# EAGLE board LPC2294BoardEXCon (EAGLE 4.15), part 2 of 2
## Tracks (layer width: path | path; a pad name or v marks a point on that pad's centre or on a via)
/CS1_RAM  (via drill 0.5)
  Top 0.254: IC1.13 34.44,22.86 v37.46,19.84 40.63,16.66 53.97,16.66 57.93,12.7 IC2.13
  Bottom 0.254: IC3.30 51.56,39.66 49.52,37.62 49.52,34.12 46.03,30.63 46.03,26.82 43.81,24.6 43.81,20.47 43.17,19.84 40.32,19.84 40,20.16 37.78,20.16 v37.46,19.84
/CS2  (via drill 0.5)
  Top 0.254: v49.21,39.2 52.7,39.2 53.65,38.25 55.88,38.25 56.83,37.3 60.64,37.3 62.54,39.2 65.08,39.2 66.35,37.94 68.26,37.94 69.53,39.2 75.88,39.2 78.1,41.43 78.1,50.63 77.78,50.95 77.78,62.7 78.1,63.02 78.1,66.83 78.73,67.46 78.73,79.84 77.78,80.8 67.94,80.8 66.67,82.07 52.38,82.07 52.06,82.38 v52.06,83.65
  Bottom 0.254: IC3.35 49.06,39.35 v49.21,39.2 | IC6.34 51.97,83.56 v52.06,83.65
/CS3  (via drill 0.5)
  Top 0.254: v48.25,38.57 48.57,38.57 48.89,38.25 50.16,38.25 51.11,37.3 52.38,37.3 54.92,34.76 60.95,34.76 62.54,33.17 76.83,33.17 77.78,32.22 78.73,32.22 81.28,34.76 81.28,37.62 82.23,38.57 SV1.39
  Bottom 0.254: IC3.36 48.56,40.15 48.25,39.84 v48.25,38.57
/OE  (via drill 0.5)
  Top 0.254: IC2.42 57.93,23.81 v54.6,27.14 51.11,30.63 42.22,30.63 38.09,34.76 35.24,34.76 34.44,35.56 IC1.42 34.44,48.56 36.51,50.63 36.51,55.4 47.94,66.83 56.83,66.83 v57.78,65.88 | v40.95,70 43.17,72.22 44.45,72.22 47.94,75.72 53.65,75.72 v53.97,76.03 | v78.42,37.94 70.16,37.94 68.89,36.66 65.72,36.66 64.45,37.94 63.18,37.94 62.54,37.3 v62.54,36.98
  Bottom 0.254: IC3.90 57.06,65.16 57.14,65.24 | v57.78,65.88 57.14,65.24 | 57.14,65.24 53.65,68.73 42.54,68.73 41.27,70 v40.95,70 | v53.97,76.03 53.65,76.03 53.34,76.35 51.75,76.35 51.54,76.55 IC6.29 | SV1.28 86.04,52.54 83.5,52.54 78.42,47.46 v78.42,37.94 | v54.6,27.14 54.6,28.41 57.14,30.95 59.05,30.95 62.22,34.12 62.22,36.66 v62.54,36.98
/RES  (via drill 0.5)
  Top 0.254: R6.2 66.04,50.95 65.72,51.27 | v80.64,46.51 80.01,46.51 79.37,45.87 79.37,34.76 78.73,34.12 77.78,34.12 76.51,35.4 v71.12,35.4
  Top 0.406: 65.72,51.27 C3.1 | R6.2 66.04,49.05 v66.35,48.73
  Bottom 0.254: v66.35,48.73 66.67,48.41 66.67,47.78 67.06,47.39 IC3.135 72.14,47.39 72.7,46.83 72.7,37.62 71.12,36.03 v71.12,35.4 | SV1.31 82.86,48.73 v80.64,46.51
/WE  (via drill 0.5)
  Top 0.254: IC1.15 36.04,22.53 v39.36,19.2 41.27,17.3 56.19,17.3 59.53,13.96 IC2.15 | v51.43,38.25 52.7,38.25 53.34,37.62 55.88,37.62 56.83,36.66 60.64,36.66 62.54,38.57 64.77,38.57 66.04,37.3 68.58,37.3 69.84,38.57 76.2,38.57 78.73,41.11 78.73,49.05 v79.05,49.37 78.73,49.68 78.73,50.63 78.42,50.95 78.42,62.7 78.73,63.02 78.73,66.83 79.37,67.46 79.37,80.8 78.73,81.43 68.26,81.43 66.67,83.02 v53.65,83.02
  Bottom 0.254: v39.36,19.2 43.81,19.2 44.45,19.84 44.45,24.6 46.67,26.82 46.67,30.63 50.16,34.12 50.16,36.98 v51.43,38.25 52.06,38.89 52.06,39.2 IC3.29 | IC6.30 50.89,80.26 v53.65,83.02 | SV1.27 83.5,53.81 v79.05,49.37
A0  (via drill 0.5)
  Top 0.254: v39.36,70 40.32,70.95 41.27,70.95 43.17,72.86 44.45,72.86 47.94,76.35 53.02,76.35 53.65,76.99 61.91,76.99 62.54,77.62 65.72,77.62 v66.67,76.67
  Bottom 0.254: IC3.89 56.56,65.19 53.65,68.1 41.27,68.1 v39.36,70 | IC6.5 67.15,77.14 v66.67,76.67 66.67,73.81 67.31,73.18 73.34,73.18 76.83,76.67 SV1.9
A1  (via drill 0.5)
  Top 0.254: v38.09,39.84 38.09,48.41 38.41,48.73 38.41,53.49 39.68,54.76 39.68,57.3 47.3,64.92 v55.56,64.92 | v35.55,67.46 35.87,67.14 42.54,67.14 47.94,72.54 63.49,72.54 v64.45,73.49 64.77,73.18 72.07,73.18 v73.02,74.13
  Bottom 0.254: SJ1.1 39.05,40.79 v38.09,39.84 | IC3.88 56.06,64.47 v55.56,64.92 53.65,66.83 41.27,66.83 40.95,67.14 35.87,67.14 v35.55,67.46 | IC6.7 65.84,74.89 v64.45,73.49 | SV1.8 86.04,77.94 76.83,77.94 v73.02,74.13
A2  (via drill 0.5)
  Top 0.254: IC2.11 56.33,11.44 52.38,15.39 39.68,15.39 32.84,22.24 IC1.11 32.84,27.28 v33.33,27.78 | v34.6,66.51 34.6,67.78 35.24,68.41 35.87,68.41 36.51,67.78 42.54,67.78 47.94,73.18 62.86,73.18 v63.18,73.49 64.13,74.45 64.77,74.45 65.4,73.81 71.43,73.81 v73.02,75.4
  Bottom 0.254: IC3.87 55.56,63.65 53.02,66.19 41.27,66.19 40.95,66.51 v34.6,66.51 | v33.33,27.78 31.75,27.78 26.35,33.17 26.35,61.43 31.43,66.51 v34.6,66.51 | v34.6,66.51 34.6,66.46 | IC6.8 65.2,75.51 v63.18,73.49 | SV1.7 76.83,79.21 v73.02,75.4
A3  (via drill 0.5)
  Top 0.254: IC2.10 55.53,11.61 52.38,14.76 39.68,14.76 32.04,22.4 IC1.10 32.04,31.88 v32.38,32.22 | v33.02,65.56 33.02,67.14 34.92,69.05 36.19,69.05 36.82,68.41 42.54,68.41 47.94,73.81 62.22,73.81 v63.18,74.77 63.49,75.08 65.08,75.08 65.72,74.45 70.8,74.45 v71.43,75.08
  Bottom 0.254: IC3.81 52.56,63.47 50.48,65.56 32.7,65.54 | 32.7,65.54 31.11,65.56 26.98,61.43 26.98,35.08 29.84,32.22 v32.38,32.22 | 32.7,65.54 32.7,65.56 v33.02,65.56 | 63.49,75.08 63.61,75.2 | v63.18,74.77 63.49,75.08 | IC6.9 64.55,76.13 63.49,75.08 | SV1.6 86.04,80.48 76.83,80.48 v71.43,75.08
A4  (via drill 0.5)
  Top 0.254: IC2.9 54.73,11.77 52.38,14.12 39.68,14.12 31.24,22.57 IC1.9 31.24,32.98 v31.43,33.17 | v61.91,74.77 61.59,74.45 47.94,74.45 42.54,69.05 37.14,69.05 36.51,69.68 34.6,69.68 32.06,67.14 v32.06,64.6 | v71.43,76.35 67.94,76.35 67.31,75.72 66.35,75.72 65.4,76.67 v63.49,76.67
  Bottom 0.254: IC3.80 52.06,63.34 50.48,64.92 38.73,64.92 38.41,64.6 v32.06,64.6 30.79,64.6 27.62,61.43 27.62,35.08 29.52,33.17 v31.43,33.17 | IC6.10 63.89,77.07 v63.49,76.67 63.49,76.35 v61.91,74.77 | SV1.5 76.83,81.75 v71.43,76.35
A5  (via drill 0.5)
  Top 0.254: IC2.8 53.93,11.94 52.38,13.49 39.68,13.49 30.44,22.73 IC1.8 30.48,27.46 30.79,27.78 30.79,32.54 30.44,32.89 30.44,34.09 v30.48,34.12
  Bottom 0.254: IC3.74 49.06,63.65 39.68,63.65 37.14,61.11 34.6,61.11 28.25,54.76 28.25,35.08 29.21,34.12 v30.48,34.12
A6  (via drill 0.5)
  Top 0.254: IC2.7 53.13,12.1 52.38,12.85 39.68,12.85 29.64,22.9 IC1.7 29.64,27.57 30.16,28.09 30.16,32.22 29.64,32.74 29.64,34.96 v29.52,35.08
  Bottom 0.254: IC3.73 39.36,62.7 37.13,60.47 34.6,60.48 28.89,54.76 28.89,35.71 v29.52,35.08
A7  (via drill 0.5)
  Top 0.254: IC2.48 53.13,24.8 50.48,27.46 42.22,27.46 38.09,31.59 34.28,31.59 29.64,36.23 IC1.48 29.64,41.54 v29.84,41.74
  Bottom 0.254: v29.84,41.74 29.52,42.06 29.52,54.76 34.6,59.84 38.09,59.84 38.64,60.39 IC3.72
A8  (via drill 0.5)
  Top 0.254: IC2.47 53.93,24.64 50.48,28.09 42.22,28.09 38.09,32.22 34.28,32.22 30.44,36.07 IC1.47 30.44,41.07 v31.11,41.74
  Bottom 0.254: IC3.71 39.09,59.89 38.41,59.21 34.6,59.21 30.16,54.76 30.16,43.65 31.11,42.7 v31.11,41.74
A9  (via drill 0.5)
  Top 0.254: IC2.46 54.73,24.47 50.48,28.73 42.22,28.73 38.09,32.86 34.28,32.86 31.24,35.9 IC1.46 31.24,40.29 v31.43,40.48
  Bottom 0.254: IC3.66 33.42,57.39 30.79,54.76 30.79,43.97 32.06,42.7 32.06,41.11 v31.43,40.48
A10  (via drill 0.5)
  Top 0.254: IC2.45 55.53,24.31 50.48,29.36 42.22,29.36 38.09,33.49 34.28,33.49 32.04,35.74 IC1.45 32.04,39.81 v32.7,40.48
  Bottom 0.254: IC3.65 33.55,56.89 31.43,54.76 31.43,43.97 33.02,42.38 33.02,40.79 v32.7,40.48
A11  (via drill 0.5)
  Top 0.254: IC2.44 56.33,24.14 50.48,30 42.22,30 38.09,34.12 34.28,34.12 32.84,35.57 IC1.44 32.84,39.06 v33.02,39.2
  Bottom 0.254: IC3.64 33.69,56.39 32.06,54.76 32.06,43.97 33.65,42.38 33.65,39.84 v33.02,39.2
A12  (via drill 0.5)
  Top 0.254: IC2.38 61.13,24.42 56.83,28.73 54.29,28.73 51.11,31.9 42.22,31.9 37.64,36.49 IC1.38 37.64,38.39 37.14,38.89 37.14,48.09 37.78,48.73 37.78,54.13 v38.73,55.08
  Bottom 0.254: IC3.63 39.54,55.89 v38.73,55.08
A13  (via drill 0.5)
  Top 0.254: IC2.37 61.93,23.04 61.91,23.01 61.91,24.28 56.83,29.36 54.29,29.36 51.11,32.54 42.22,32.54 38.44,36.32 IC1.37 38.44,38.28 39.05,38.89 39.05,53.49 v40.63,55.08
  Bottom 0.254: IC3.62 40.94,55.39 v40.63,55.08
A14  (via drill 0.5)
  Top 0.254: IC2.36 62.73,24.09 56.83,30 54.29,30 51.11,33.17 42.22,33.17 39.24,36.16 IC1.36 39.24,38.13 39.68,38.57 39.68,52.22 v40,52.54
  Bottom 0.254: IC3.56 40.16,52.39 v40,52.54
A15  (via drill 0.5)
  Top 0.254: IC2.35 63.53,23.93 56.83,30.63 54.29,30.63 51.11,33.81 42.22,33.81 40.04,35.99 IC1.35 40.04,37.97 40.32,38.25 40.32,51.27 v40.63,51.59
  Bottom 0.254: IC3.55 40.93,51.89 v40.63,51.59
A16  (via drill 0.5)
  Top 0.254: IC2.34 64.33,23.76 56.83,31.27 54.29,31.27 51.11,34.44 42.22,34.44 40.95,35.71 40.95,36.98 40.9,37.03 | 40.9,37.03 IC1.34 | 40.9,37.03 40.9,50.27 v41.27,50.63
  Bottom 0.254: IC3.53 41.52,50.89 v41.27,50.63
A17  (via drill 0.5)
  Top 0.254: IC2.21 64.33,12.33 56.83,19.84 41.9,19.84 40.63,21.11 40.63,23.96 40.84,24.17 IC1.21 40.84,28.21 38.09,30.95 33.65,30.95 v33.33,31.27
  Bottom 0.254: v33.33,31.27 34.6,32.54 34.6,46.19 36.8,48.39 IC3.48
A18  (via drill 0.5)
  Top 0.254: IC2.20 63.53,12.5 56.83,19.2 41.9,19.2 40.04,21.07 IC1.20 40.04,28.37 38.09,30.32 34.92,30.32 v34.6,30
  Bottom 0.254: IC3.47 37.25,47.89 35.24,45.87 35.24,30.63 v34.6,30
A19  (via drill 0.5)
  Top 0.254: IC2.19 62.73,12.66 56.83,18.57 41.9,18.57 39.24,21.23 IC1.19 39.24,28.54 38.09,29.68 36.19,29.68 v35.87,29.36
  Bottom 0.254: IC3.46 37.39,47.39 35.87,45.87 v35.87,29.36
A20  (via drill 0.5)
  Top 0.254: IC2.18 61.93,12.83 56.83,17.93 41.9,17.93 38.44,21.4 IC1.18 38.44,28.39 38.09,28.73 v37.14,28.73
  Bottom 0.254: IC3.45 37.52,46.89 36.51,45.87 36.51,30 37.14,29.36 v37.14,28.73
A21  (via drill 0.5)
  Top 0.254: v47.94,35.4 48.25,35.08 51.11,35.08 54.29,31.9 56.83,31.9 61.91,26.82 v62.54,26.82 | IC2.17 61.13,10.17 v61.27,10
  Bottom 0.254: 39.05,45.55 SJ1.3 | IC3.44 39.56,46.39 39.05,45.87 39.05,45.55 | 39.05,45.55 40,45.55 40.32,45.24 40.32,39.84 43.49,36.66 46.67,36.66 v47.94,35.4 | v62.54,26.82 62.54,18.25 60.95,16.66 60.95,12.54 61.27,12.22 v61.27,10
AN0  (via drill 0.5)
  Top 0.254: v56.19,42.38 56.19,38.89 57.14,37.94 60.32,37.94 62.22,39.84 65.72,39.84 v66.35,39.2 | v67.94,27.78 68.58,28.41 78.73,28.41 81.28,30.95 SV1.45
  Bottom 0.254: IC3.23 55.06,41.88 55.56,42.38 v56.19,42.38 | v66.35,39.2 68.26,37.3 68.26,28.41 67.94,28.09 v67.94,27.78
BLS0  (via drill 0.5)
  Top 0.254: v59.68,65.88 59.05,65.88 58.1,64.92 57.46,64.92 56.19,66.19 47.94,66.19 37.14,55.4 37.14,48.73 36.51,48.09 36.51,38.57 36.82,38.25 36.82,36.98 | v78.42,35.4 78.1,35.4 77.15,36.35 70.48,36.35 69.53,35.4 v63.18,35.4 | v55.88,27.78 55.56,28.09 54.29,28.09 51.11,31.27 42.22,31.27 38.09,35.4 37.14,35.4 36.82,35.71 36.82,36.98 | 36.82,36.98 36.84,36.99 IC1.39
  Bottom 0.254: IC3.96 60.06,65.5 v59.68,65.88 | SV1.30 86.04,50 82.86,50 79.69,46.83 79.69,38.89 80.01,38.57 80.01,36.66 78.73,35.4 v78.42,35.4 | v63.18,35.4 63.18,34.44 59.05,30.32 57.14,30.32 55.88,29.05 v55.88,27.78
BLS1  (via drill 0.5)
  Top 0.254: v33.97,26.51 33.65,26.19 33.65,25.23 33.64,25.22 IC1.12 33.64,22.07 39.68,16.03 53.34,16.03 v53.97,15.39 | v78.42,36.66 77.78,36.66 77.47,36.98 70.16,36.98 69.21,36.03 65.08,36.03 v64.45,36.66 | v60.32,21.11 59.68,20.47 49.21,20.47 48.89,20.79 v48.57,20.79
  Bottom 0.254: IC3.97 60.56,66.27 60,66.83 56.19,66.83 53.34,69.68 42.54,69.68 41.27,70.95 35.24,70.95 25.71,61.43 25.71,33.17 32.06,26.82 33.65,26.82 v33.97,26.51 | SV1.29 83.18,51.27 79.05,47.14 79.05,38.89 79.37,38.57 79.37,37.62 v78.42,36.66 | v64.45,36.66 64.77,36.35 64.77,33.81 63.18,32.22 63.18,28.73 60.95,26.51 60.95,21.74 v60.32,21.11 | v48.57,20.79 48.57,16.35 48.89,16.03 53.34,16.03 v53.97,15.39
BLS2  (via drill 0.5)
  Top 0.254: v53.65,33.81 53.65,33.17 54.29,32.54 56.83,32.54 60,29.36 v60.64,29.36 | v60,24.28 60.32,23.96 60.32,23.01 60.33,23.03 IC2.39
  Bottom 0.254: v60,24.28 60,28.73 v60.64,29.36 | IC3.27 53.06,34.4 v53.65,33.81
BLS3  (via drill 0.5)
  Top 0.254: v46.35,6.18 46.98,5.55 56.19,5.55 57.14,6.5 57.14,10.95 57.13,10.96 IC2.12
  Bottom 0.254: IC3.28 52.56,38.12 50.79,36.35 50.79,34.12 47.3,30.63 47.3,26.82 45.08,24.6 45.08,12.85 44.76,12.54 44.76,6.82 45.4,6.18 v46.35,6.18
CLOCK  (via drill 0.5)
  Top 0.254: v33.65,54.45 27.62,54.45 26.98,53.81 26.98,48.41 25.08,46.51 v22.22,46.51 | MMC1.3 20.41,68.64 v20.63,68.41
  Bottom 0.254: IC3.59 41.98,53.89 41.59,53.49 34.6,53.49 v33.65,54.45 | v22.22,46.51 20.63,48.09 v20.63,68.41
CS_CARD  (via drill 0.5)
  Top 0.254: v37.46,62.7 37.46,62.38 33.97,58.89 28.57,58.89 22.22,52.54 v22.22,50 | MMC1.7 22.15,58.64 v22.22,58.57
  Bottom 0.254: IC3.78 51.06,63.38 50.16,64.29 39.05,64.29 v37.46,62.7 | v22.22,50 21.9,50.32 21.9,58.26 v22.22,58.57 22.54,58.89 22.54,61.43 26.98,65.88 R14.1
D0  (via drill 0.5)
  Top 0.254: IC1.22 41.64,23.6 v41.59,23.65 | v75.24,73.81 75.88,74.45 75.88,77.62 75.24,78.26 49.21,78.26 44.76,73.81 43.49,73.81 41.9,72.22 v38.73,72.22 38.41,72.54 R16.1
  Bottom 0.254: IC3.98 61.06,66.4 60,67.46 56.19,67.46 53.02,70.64 45.71,70.64 45.4,70.32 42.54,70.32 40.63,72.22 v38.73,72.22 35.87,72.22 25.08,61.43 25.08,33.17 35.24,23.01 40.95,23.01 v41.59,23.65 | v75.24,73.81 76.83,75.4 85.4,75.4 86.67,76.67 SV1.10 87.94,76.67 88.26,76.99 88.26,77.94 89.53,79.21 D1.A
D1  (via drill 0.5)
  Top 0.254: IC1.24 43.24,23.9 v42.86,23.65 | v76.2,73.18 76.51,73.49 76.51,78.57 76.2,78.89 49.21,78.89 44.76,74.45 43.49,74.45 42.22,73.18 v39.68,73.18 R17.1
  Bottom 0.254: IC3.105 64.56,65.44 60.95,68.73 56.19,68.73 53.02,71.91 44.76,71.91 43.49,73.18 v39.68,73.18 36.19,73.18 24.44,61.43 24.44,33.17 35.24,22.38 41.59,22.38 v42.86,23.65 | v76.2,73.18 77.15,74.13 SV1.11 85.4,74.13 86.67,75.4 87.94,75.4 89.53,76.99 D2.A
D2  (via drill 0.5)
  Top 0.254: IC1.25 44.04,23.56 v42.54,22.06 | v76.83,72.22 77.15,72.54 77.15,78.89 76.51,79.53 49.21,79.53 44.76,75.08 43.49,75.08 42.54,74.13 v40.63,74.13 40.63,75.72 40.95,76.03 R18.1
  Bottom 0.254: IC3.106 65.06,65.58 60.95,69.37 56.19,69.37 53.02,72.54 45.08,72.54 43.49,74.13 v40.63,74.13 36.51,74.13 23.81,61.43 23.81,33.17 35.24,21.74 42.22,21.74 v42.54,22.06 | v76.83,72.22 77.47,72.86 85.4,72.86 86.67,74.13 SV1.12 87.94,74.13 88.58,74.77 D3.A 89.85,74.77
D3  (via drill 0.5)
  Top 0.254: IC1.27 45.64,21.82 44.76,20.79 v42.22,20.79 | v77.78,71.59 77.78,79.21 76.83,80.16 49.21,80.16 44.76,75.72 43.49,75.72 42.86,75.08 v41.59,75.08 41.59,76.99 42.22,77.62 R19.1
  Bottom 0.254: IC3.108 66.06,63.62 65.72,63.97 65.75,65.53 60.95,70 56.19,70 53.02,73.18 45.4,73.18 43.49,75.08 v41.59,75.08 36.82,75.08 23.17,61.43 23.17,33.17 35.24,21.11 41.9,21.11 v42.22,20.79 | v77.78,71.59 SV1.13 85.4,71.59 86.67,72.86 88.58,72.86 88.9,72.54 D4.A
D4  (via drill 0.5)
  Top 0.254: IC1.28 45.64,38.33 43.49,40.48 43.49,49.68 44.13,50.32 44.13,59.21 47.3,62.38 53.97,62.38 54.6,61.75 62.54,61.75 63.18,62.38 68.26,62.38 68.58,62.06 v68.58,61.43 | v73.97,70.32 v77.78,70.32 | v42.54,76.03 42.54,76.35 43.49,77.3 R21.1
  Bottom 0.254: v42.54,76.03 43.49,76.03 45.71,73.81 53.02,73.81 56.19,70.64 73.66,70.64 v73.97,70.32 73.66,70 73.66,63.97 71.12,61.43 v68.58,61.43 68.36,61.22 IC3.109 | v77.78,70.32 85.4,70.32 86.67,71.59 SV1.14 87.94,71.59 89.21,70.32 D5.A 89.85,70.32
D5  (via drill 0.5)
  Top 0.254: IC1.30 44.04,39.29 42.86,40.48 42.86,49.68 43.49,50.32 43.49,59.21 47.3,63.02 54.29,63.02 54.92,62.38 62.22,62.38 62.86,63.02 69.21,63.02 69.84,62.38 v69.84,58.89 | v77.78,69.05 77.47,69.37 v74.93,69.37 | R22.1 44.45,79.84 v44.45,77.3
  Bottom 0.254: IC3.114 68.84,57.89 v69.84,58.89 74.29,63.34 74.29,68.73 v74.93,69.37 74.93,70.64 74.29,71.27 56.19,71.27 53.02,74.45 46.03,74.45 44.45,76.03 v44.45,77.3 | v77.78,69.05 SV1.15 85.4,69.05 86.67,70.32 87.94,70.32 88.58,69.68 88.58,69.05 89.53,68.1 D6.A
D6  (via drill 0.5)
  Top 0.254: v71.12,58.89 71.43,59.21 71.43,62.38 67.94,65.88 62.54,65.88 60,63.34 54.92,63.34 54.6,63.65 47.3,63.65 42.86,59.21 42.86,50.32 42.22,49.68 42.22,40.48 43.49,39.2 43.49,38.25 43.24,38 IC1.31 | v77.78,67.78 76.51,67.78 v75.88,68.41 | v45.4,78.26 45.4,78.57 46.03,79.21 R23.1
  Bottom 0.254: IC3.115 69.61,57.39 v71.12,58.89 74.93,62.7 74.93,67.46 v75.88,68.41 75.88,70.95 74.93,71.91 56.19,71.91 53.02,75.08 46.98,75.08 45.4,76.67 v45.4,78.26 | v77.78,67.78 85.4,67.78 86.67,69.05 SV1.16 87.62,69.05 89.21,67.46 89.21,66.19 89.53,65.88 D7.A 90.17,65.88
D7  (via drill 0.5)
  Top 0.254: IC1.33 41.64,49.73 42.22,50.32 42.22,59.21 47.3,64.29 54.92,64.29 55.24,63.97 59.68,63.97 62.22,66.51 67.94,66.51 72.07,62.38 72.07,58.57 v71.12,57.62 | v47.3,79.84 R24.1
  Bottom 0.254: IC3.116 70.38,56.89 v71.12,57.62 75.56,62.06 75.56,66.19 76.83,67.46 | v47.3,79.84 47.3,77.94 49.52,75.72 53.02,75.72 56.19,72.54 75.24,72.54 76.83,70.95 76.83,67.46 | 76.83,67.46 77.47,66.83 78.42,66.83 78.73,67.14 82.55,67.14 83.18,66.51 SV1.17 85.09,66.51 86.36,67.78 87.94,67.78 88.58,67.14 88.58,64.29 89.21,63.65 D8.A 90.17,63.65
D8  (via drill 0.5)
  Top 0.254: v72.39,57.62 72.7,57.94 72.7,62.38 67.62,67.46 47.94,67.46 35.87,55.4 35.87,50.63 28.84,43.6 IC1.49
  Bottom 0.254: IC3.117 71.15,56.39 v72.39,57.62 76.2,61.43 76.2,63.97 76.83,64.6 78.73,64.6 79.37,65.24 86.04,65.24 SV1.18
D9  (via drill 0.5)
  Top 0.254: 63.18,68.1 47.94,68.1 35.24,55.4 35.24,50.63 27.24,42.63 IC1.51 | 63.18,68.1 63.49,68.1 | 63.18,68.1 67.62,68.1 73.34,62.38 73.34,57.3 v72.39,56.35
  Bottom 0.254: IC3.118 71.92,55.89 v72.39,56.35 79.37,63.34 83.18,63.34 83.81,63.97 SV1.19
D10  (via drill 0.5)
  Top 0.254: v73.66,56.35 73.97,56.67 73.97,62.38 67.62,68.73 47.94,68.73 34.6,55.4 34.6,50.63 26.44,42.47 IC1.52
  Bottom 0.254: IC3.120 72.19,54.89 v73.66,56.35 80.01,62.7 86.04,62.7 SV1.20
D11  (via drill 0.5)
  Top 0.254: v73.34,52.86 74.61,54.13 74.61,62.38 67.62,69.37 47.94,69.37 42.22,63.65 37.14,63.65 33.02,59.52 28.57,59.52 20.63,51.59 20.63,39.84 23.44,37.03 IC1.54 24.84,37.22
  Bottom 0.254: IC3.124 73.37,52.89 v73.34,52.86 74.61,54.13 76.2,54.13 83.5,61.43 SV1.21
D12  (via drill 0.5)
  Top 0.254: IC1.1 24.84,35 20,39.84 20,51.59 28.57,60.16 33.02,60.16 37.14,64.29 42.22,64.29 47.94,70 67.62,70 75.24,62.38 75.24,53.18 v74.93,52.86
  Bottom 0.254: SV1.22 86.04,60.16 83.5,60.16 76.51,53.18 75.24,53.18 v74.93,52.86 73.82,51.75 71.9,51.75 71.27,52.39 IC3.125
D13  (via drill 0.5)
  Top 0.254: v74.93,51.59 75.88,52.54 75.88,62.38 67.62,70.64 47.94,70.64 42.54,65.24 37.14,65.24 32.7,60.8 28.57,60.8 19.36,51.59 19.36,39.84 23.81,35.4 23.81,23.96 24.76,23.01 26.03,23.01 26.67,23.65 26.67,24.28 26.44,24.51 IC1.3
  Bottom 0.254: SV1.23 83.5,58.89 76.83,52.22 75.56,52.22 v74.93,51.59 74.41,51.07 71.63,51.07 71.31,51.39 IC3.127
D14  (via drill 0.5)
  Top 0.254: IC1.4 27.24,23.27 26.35,22.38 24.44,22.38 23.17,23.65 23.17,35.4 18.73,39.84 18.73,51.59 28.57,61.43 32.7,61.43 37.14,65.88 42.54,65.88 47.94,71.27 67.62,71.27 76.51,62.38 76.51,51.59 v75.88,50.95
  Bottom 0.254: IC3.129 75.31,50.39 v75.88,50.95 | v75.88,50.95 76.2,50.95 | SV1.24 86.04,57.62 83.5,57.62 76.83,50.95 v75.88,50.95
D15  (via drill 0.5)
  Top 0.254: IC1.6 28.84,22.64 27.94,21.74 24.12,21.74 22.54,23.33 22.54,35.4 18.09,39.84 18.09,51.59 28.57,62.06 32.7,62.06 37.14,66.51 42.54,66.51 47.94,71.91 67.62,71.91 77.15,62.38 77.15,50.95 v75.88,49.68
  Bottom 0.254: IC3.130 75.67,49.89 v75.88,49.68 | v75.88,49.68 76.2,49.68 | SV1.25 83.5,56.35 76.83,49.68 v75.88,49.68
D16  (via drill 0.5)
  Top 0.254: IC2.22 65.13,13.54 v65.08,13.49
  Bottom 0.254: v65.08,13.49 65.72,13.49 74.29,22.06 74.29,36.66 75.24,37.62 75.24,48.73 74.59,49.39 IC3.131
D17  (via drill 0.5)
  Top 0.254: IC2.24 66.73,15.77 v66.67,15.71
  Bottom 0.254: IC3.132 73.81,48.89 74.61,48.09 74.61,37.62 73.66,36.66 73.66,22.06 67.31,15.71 v66.67,15.71
D18  (via drill 0.5)
  Top 0.254: IC2.25 67.53,14.67 67.62,14.76 v67.62,17.93
  Bottom 0.254: IC3.133 73.36,48.39 73.97,47.78 73.97,37.62 73.02,36.66 73.02,22.06 68.89,17.93 v67.62,17.93
D19  (via drill 0.5)
  Top 0.254: IC2.27 69.13,19.44 v69.53,19.84
  Bottom 0.254: IC3.134 72.59,47.89 73.34,47.14 73.34,37.62 72.39,36.66 72.39,22.06 70.16,19.84 v69.53,19.84
D20  (via drill 0.5)
  Top 0.254: IC2.28 69.13,23.25
  Top 0.406: 69.13,23.25 69.13,23.01 v70.48,23.01
  Bottom 0.254: IC3.136 71.37,46.89 72.07,46.19 72.07,37.62 70.16,35.71 70.16,28.09 70.48,27.78 v70.48,23.01
D21  (via drill 0.5)
  Top 0.254: IC2.30 67.53,23.88 69.21,25.55 v69.53,25.55
  Bottom 0.254: IC3.137 70.92,46.39 71.43,45.87 71.43,37.62 69.53,35.71 v69.53,25.55
D22  (via drill 0.5)
  Top 0.254: IC2.31 66.73,25.49 v66.67,25.55
  Bottom 0.254: IC3.1 66.06,40.77 67.28,40.77 67.31,40.79 68.89,38.89 68.92,27.43 66.99,25.55 v66.67,25.55
D23  (via drill 0.5)
  Top 0.254: IC2.33 65.13,23.91 63.49,25.55 63.49,27.14 62.22,28.41 v61.59,28.41
  Bottom 0.254: 62.2,39.23 62.22,39.2 | 62.2,39.23 61.56,39.87 IC3.10 | v61.59,28.41 62.22,29.05 62.22,31.9 64.13,33.81 64.13,35.71 63.49,36.35 63.49,37.94 62.2,39.23
D24  (via drill 0.5)
  Top 0.254: IC2.49 52.33,24.23 v52.38,24.28
  Bottom 0.254: 60.95,33.49 59.05,31.59 57.14,31.59 52.38,26.82 v52.38,24.28 | 60.95,33.49 61.06,33.6 | 60.95,33.49 61.59,34.12 61.59,39.2 61.06,39.73 IC3.11
D25  (via drill 0.5)
  Top 0.254: IC2.51 50.79,23.01 v50.79,21.74
  Bottom 0.254: v50.79,21.74 50.79,23.96 51.75,24.92 51.75,26.82 57.14,32.22 59.05,32.22 60.95,34.12 60.95,39.2 60.56,39.6 IC3.12
D26  (via drill 0.5)
  Top 0.254: IC2.52 49.93,24.37 v49.84,24.28
  Bottom 0.254: 60,33.81 59.05,32.86 57.14,32.86 51.11,26.82 51.11,25.55 v49.84,24.28 | 60,33.81 60.06,33.87 | 60,33.81 60.32,34.12 60.32,39.2 60.06,39.46 IC3.13
D27  (via drill 0.5)
  Top 0.254: IC2.54 48.33,24.04 v48.57,24.28
  Bottom 0.254: IC3.16 58.56,34.91 48.57,24.92 v48.57,24.28
D28  (via drill 0.5)
  Top 0.254: 48.33,11.19 IC2.1 48.33,10.71 48.25,10.63 v47.62,10.63
  Bottom 0.254: IC3.17 58.06,35.04 47.62,24.6 v47.62,10.63
D29  (via drill 0.5)
  Top 0.254: IC2.3 49.93,9.77 v49.52,9.36
  Bottom 0.254: IC3.18 57.56,35.18 46.98,24.6 46.98,12.85 46.67,12.54 46.67,9.68 47.62,8.73 48.89,8.73 v49.52,9.36
D30  (via drill 0.5)
  Top 0.254: IC2.4 50.73,8.98 49.84,8.09 v46.98,8.09
  Bottom 0.254: IC3.19 57.06,35.31 46.35,24.6 46.35,12.85 46.03,12.54 46.03,9.04 v46.98,8.09
D31  (via drill 0.5)
  Top 0.254: IC2.6 52.33,9.63 49.84,7.14 v48.25,7.14
  Bottom 0.254: IC3.20 56.56,35.45 45.71,24.6 45.71,12.85 45.4,12.54 45.4,7.77 46.03,7.14 v48.25,7.14
DATA_IN  (via drill 0.5)
  Top 0.254: v34.92,58.26 28.57,58.26 22.86,52.54 22.86,50.95 23.17,50.63 23.17,49.05 22.86,48.73 v22.22,48.73 | MMC1.6 21.56,61.14 v21.59,61.11
  Bottom 0.254: IC3.68 35.05,58.39 v34.92,58.26 | v22.22,48.73 21.27,49.68 21.27,60.8 v21.59,61.11
DATA_OUT  (via drill 0.5)
  Top 0.254: v33.02,53.49 28.25,53.49 27.62,52.86 27.62,48.09 24.76,45.24 v22.22,45.24 | MMC1.1 19.54,73.64 v19.68,73.49
  Bottom 0.254: IC3.61 41.71,54.89 40.95,54.13 38.09,54.13 36.51,55.72 33.65,55.72 32.7,54.76 32.7,53.81 v33.02,53.49 | v22.22,45.24 20,47.46 20,67.46 19.68,67.78 v19.68,73.49
EINT0  (via drill 0.5)
  Top 0.254: v63.18,64.92 v67.62,64.92 | v71.75,69.37 72.7,69.37 v76.51,65.56 | v80.01,66.19 80.32,66.19 82.23,64.29 82.23,57.3 81.59,56.67 81.59,52.22 82.55,51.27 82.55,50.63 83.18,50 86.04,50 SV1.32
  Bottom 0.254: IC3.100 62.06,63.81 v63.18,64.92 | v67.62,64.92 69.53,64.92 70.16,65.56 70.16,67.78 v71.75,69.37 | v76.51,65.56 78.42,65.56 79.05,66.19 v80.01,66.19
GND  (via drill 0.5)
  Top 0.254: IC1.26 44.84,25.95 44.76,26.19 46.67,26.19 46.67,21.11 47.3,20.47 | v47.94,51.59 48.25,51.59 | v45.08,43.33 44.76,43.02 | v53.65,42.06 53.65,42.38 | v64.77,42.06 65.08,42.06 | v62.22,41.74 62.22,42.06 | v66.99,45.24 66.99,44.92 | v67.31,50.95 66.99,50.95 | v66.35,59.52 66.99,59.52 | C27.1 18.41,36.98 | v29.21,21.74 29.21,21.43 | 51.43,88.42 52.38,88.42 | C35.2 55.37,86.96 v55.24,86.83 | IC1.32 42.44,38.79 v42.54,38.89 | IC2.53 49.13,22.14 v49.52,21.74 | v54.92,14.44 v56.83,12.54 | v58.1,60.48 58.1,54.13 v58.41,53.81 | 55.56,54.13 v55.88,53.81
  Top 0.305: v65.08,61.11 64.77,61.11 | IC1.53 25.64,29.44 v25.71,29.36 | IC1.41 35.24,48.09 v36.19,49.05 | v44.45,49.37 44.45,49.05
  Bottom 0.254: IC3.79 51.56,61.3 v51.75,61.11 | IC3.93 58.56,60.97 v58.1,60.48 | IC3.67 47.89,57.89 v47.94,57.3 | IC3.54 47.74,51.39 v47.94,51.59 | IC3.38 45.13,43.39 v45.08,43.33 | IC3.26 53.56,41.97 v53.65,42.06 | IC3.3 65.06,41.73 v64.77,42.06 | IC3.9 62.06,41.58 v62.22,41.74 | v66.99,45.24 67.14,45.39 IC3.139 68.26,45.49 68.26,45.78 IC3.138 | IC3.128 67.37,50.89 v67.31,50.95 | IC3.111 66.53,59.39 v66.35,59.52 | v25.71,29.36 v27.62,27.46 27.62,23.33 v29.21,21.74 | 51.43,98.58 51.54,98.46 IC6.52 51.54,95.92 51.75,95.72 | IC6.92 74.27,86.81 74.29,86.83 75.88,86.83 R11.1 | IC6.14 61.27,79.84 61.59,80.16 61.91,80.16 | IC6.13 61.95,80.16 | IC6.44 49.79,90.06 | v55.24,86.83 54.92,86.83 | 59.37,95.4 59.34,95.42 59.34,95.72 59.37,95.72 59.34,95.74 IC6.64 | IC6.83 73.86,92.66 73.97,92.54 | 73.97,90.96 73.72,90.71 IC6.86 72.7,90.64 75.56,90.64 75.88,90.32 75.88,88.73 75.56,88.42 74.93,88.42 74.62,88.11 IC6.90 73.97,88.11 73.97,88.1 | 73.97,90.32 73.66,90 72.7,90 72.64,89.94 IC6.88 73.69,89.41 73.97,89.69 | v42.54,38.89 42.22,39.2 | v49.52,21.74 49.52,21.43 49.84,21.11 49.84,17.93 50.79,16.98 54.6,16.98 55.24,16.35 55.24,14.76 v54.92,14.44 | v56.83,12.54 56.51,12.54 | 56.09,80.16 IC6.22 | IC6.22 56.09,76.13 56.19,76.03 | 56.19,76.03 56.83,75.4 | IC6.22 56.09,78.35 56.19,78.26 56.19,76.03 | IC3.103 63.56,61.5 62.86,60.8 v61.27,60.8 | v55.88,53.81 v58.41,53.81
  Bottom 0.305: IC3.107 65.56,61.59 v65.08,61.11 | v36.19,49.05 43.81,49.05 44.13,49.37 v44.45,49.37 | v27.62,27.46 v25.71,29.36
  Bottom 0.406: v27.62,27.46 26.98,26.82 | IC6.19 58.04,80.16 57.78,80.16 | 57.78,80.16 57.46,80.16 | 57.39,80.16 57.78,80.16 | 57.39,80.16 IC6.20 | 57.14,80.16 57.39,80.16 | 57.14,80.16 56.83,80.16 | 56.74,80.16 57.14,80.16 | 56.74,80.16 IC6.21 | 56.51,80.16 56.74,80.16 | 56.51,80.16 56.19,80.16 | 56.51,80.16 56.09,80.16 55.88,80.16 | 55.88,80.16 55.56,80.16 | 55.45,80.16 55.88,80.16 | 55.45,80.16 IC6.23 | 55.24,80.16 55.45,80.16 | 55.24,80.16 54.92,80.16 | 54.79,80.16 55.24,80.16 | 54.79,80.16 IC6.24 | 54.14,80.16 54.79,80.16 | 54.14,80.16 IC6.25 | 53.49,80.16 54.14,80.16 | 53.49,80.16 IC6.26 | 52.84,80.16 53.49,80.16 | IC6.27 52.84,80.16 | IC6.28 52.2,80.16 52.84,80.16 | 61.95,80.16 61.91,80.16 63.24,80.16 IC6.11
  pour Top (isolate 0.305): 95.88,99.53 95.88,0.47 0.31,0.47 0.31,99.53
  pour Bottom (isolate 0.305): 0.31,99.53 95.88,99.53 95.88,0.47 0.31,0.47
INT_N  (via drill 0.5)
  Top 0.254: v68.26,75.4 67.94,75.08 66.04,75.08 65.4,75.72 61.59,75.72 60.95,75.08 47.94,75.08 44.13,71.27 v43.49,71.27
  Bottom 0.254: IC3.99 61.56,66.54 60,68.1 56.19,68.1 53.02,71.27 v43.49,71.27 | IC6.4 67.8,75.89 v68.26,75.4
MISO1  (via drill 0.5)
  Top 0.254: SV1.34 86.04,44.92 83.18,44.92 82.86,45.24 82.86,47.14 81.28,48.73 81.28,50.63 80.32,51.59 80.32,57.3 80.96,57.94 80.96,60.8 v80.64,61.11
  Bottom 0.254: IC3.121 72.33,54.39 73.02,55.08 73.66,55.08 79.69,61.11 v80.64,61.11
MOSI1  (via drill 0.5)
  Top 0.254: SV1.35 82.86,43.65 82.23,44.29 82.23,47.14 80.64,48.73 80.64,50.63 79.69,51.59 79.69,57.3 80.32,57.94 80.32,59.52 v80.01,59.84
  Bottom 0.254: IC3.122 72.46,53.89 73.02,54.45 73.66,54.45 79.05,59.84 v80.01,59.84
N$1  (via drill 0.5)
  Top 0.254: IC1.17 37.64,26.33 37.46,26.51 v37.46,27.46
  Bottom 0.254: SJ1.2 37.78,43.97 37.14,43.33 37.14,30.32 38.09,29.36 38.09,28.09 v37.46,27.46
N$2  (via drill 0.6)
  Top 0.406: v2.54,16.03 LED1.C
  Bottom 0.406: v2.54,16.03 R8.2
N$3
  Top 0.406: 35.55,72.23 LED4.C | R15.2 35.55,72.23 | 35.55,72.23 35.55,72.22
N$4  (via drill 0.5)
  Top 0.254: R16.2 v38.41,83.97
  Bottom 0.254: v38.41,83.97 38.73,83.97 39.05,83.65 43.49,83.65 44.7,84.86 IC6.36
N$5  (via drill 0.5)
  Top 0.254: v47.3,59.21 R20.2
  Bottom 0.254: IC3.69 46.98,58.89 v47.3,59.21
N$6
  Top 0.254: Q1.2 70.16,40.16 70.58,40.58 C7.1
  Bottom 0.254: IC3.142 68.97,43.89 70.16,42.7 Q1.2
N$7
  Top 0.254: Q1.1 70.8,45.87 C6.1
  Bottom 0.254: Q1.1 70.16,44.92 69.63,44.39 IC3.141
N$8  (via drill 0.5)
  Top 0.254: v45.08,45.55 45.08,48.41 45.4,48.73 45.4,49.68 44.76,50.32 44.76,59.21 46.67,61.11 v47.62,61.11 | v22.22,43.97 21.59,43.97 21.27,44.29 21.27,47.14 21.9,47.78 23.17,47.78 23.81,48.41 23.81,50.63 23.49,50.95 23.49,52.54 28.57,57.62 33.97,57.62 34.28,57.3 35.24,57.3 v39.36,61.43
  Bottom 0.254: IC3.42 45.25,45.39 v45.08,45.55 | v39.36,61.43 39.68,61.11 v47.62,61.11 | IC7.10 20.32,33.17 20,33.49 20,35.71 21.59,37.3 21.59,42.06 21.27,42.38 21.27,43.65 21.59,43.97 v22.22,43.97
N$9  (via drill 0.5)
  Top 0.254: v33.02,51.27 24.12,42.7 v22.22,42.7
  Bottom 0.254: IC3.49 45.56,48.89 45.4,49.05 45.4,49.68 44.76,50.32 43.49,50.32 42.86,49.68 37.14,49.68 36.82,50 33.97,50 v33.02,51.27 | v22.22,42.7 22.22,34.44 IC7.9
N$10  (via drill 3.2)
  other vias: 90.48,96.67
N$11  (via drill 3.2)
  other vias: 90.17,16.66
N$12
  Top 0.406: IC4.1 25.31,14.67 25.39,14.76 R2.2 27.8,14.89 27.94,14.76 R5.1
N$13
  Top 0.406: J2.1-1 17.78,94.13 20,91.91 29.52,91.91 31.75,89.69 36.51,89.69 38.09,88.1 U$1.12
N$14
  Top 0.406: J2.1-2 17.78,92.86 19.68,90.96 28.89,90.96 U$1.10
N$15
  Bottom 0.406: J2.1-3 17.46,91.59 19.36,89.69 22.54,89.69 U$1.9
N$16
  Bottom 0.406: J2.1-6 18.09,87.78 19.05,86.83 U$1.7
N$17  (via drill 0.5)
  Top 0.406: IC5.1 36.9,10.71 36.82,10.63 v34.92,10.63
  Bottom 0.406: 36.38,12.22 R3.2 | 36.38,12.22 36.38,12.09 | 36.51,11.58 35.55,10.63 v34.92,10.63 | 36.38,12.22 36.51,12.22 36.51,11.58 | R4.1 37.33,10.76 36.51,11.58
N$18  (via drill 0.5)
  Top 0.254: v41.59,89.05 45.08,92.54 53.97,92.54 v55.24,93.81
  Bottom 0.254: U$1.6 20.32,92.86 21.59,91.59 23.81,91.59 24.91,90.49 R7.2 33.48,90.49 34.6,89.37 40.32,89.37 40.63,89.05 v41.59,89.05 | IC6.58 55.45,94.02 v55.24,93.81
N$19  (via drill 0.5)
  Top 0.254: v17.14,25.55 C28.1
  Bottom 0.254: IC7.1 v17.14,25.55
N$20  (via drill 0.5)
  Top 0.254: C29.1 18.41,29.05 v17.14,29.05
  Bottom 0.254: IC7.4 16.82,29.36 v17.14,29.05
N$21  (via drill 0.5)
  Top 0.254: C29.2 18.41,30.95 v17.14,30.95
  Bottom 0.254: IC7.5 16.82,30.63 v17.14,30.95
N$22
  Bottom 0.254: IC7.2 17.78,26.82 18.41,26.19 18.41,23.96 19.05,23.33 C20.2
N$23  (via drill 0.5)
  Top 0.254: C27.2 18.41,33.49 17.46,32.54 v17.14,32.54
  Bottom 0.254: IC7.6 16.51,31.9 v17.14,32.54
N$24
  Bottom 0.406: X1.2 12.69,31.9 13.96,33.17 IC7.7
N$25
  Bottom 0.406: 15.55,34.44 IC7.8 X1.3
N$26  (via drill 0.5)
  Top 0.254: v40.95,90 44.13,93.18 53.34,93.18 54.92,94.77 v56.19,94.77
  Bottom 0.254: U$1.4 26.51,93.33 R7.1 29.69,93.33 31.43,91.59 33.33,91.59 34.92,90 v40.95,90 | IC6.59 56.09,94.86 v56.19,94.77
N$27  (via drill 0.5)
  Top 0.254: v40,91.91 33.65,91.91 33.02,92.54 U$1.3
  Bottom 0.254: IC6.46 46.59,91.36 46.03,91.91 v40,91.91
N$28
  Bottom 0.254: IC6.45 46.28,90.71 45.71,91.27 40.95,91.27 40.63,90.96 38.73,90.96 38.09,91.59 U$1.1
N$29  (via drill 0.5)
  Top 0.254: v19.05,27.46 19.68,26.82 19.68,25.87 20,25.55 C28.2
  Bottom 0.254: IC7.3 16.82,28.09 17.46,27.46 v19.05,27.46
N$30
  Top 0.406: C33.1 35.37,97.81 35.55,97.62 U$1.2
N$31
  Bottom 0.813: B1.AC2 17.14,4.92 18.09,5.87 18.09,11.58 17.14,12.54 8.25,12.54 7.06,11.35 7.06,8.81 6.94,8.69 X2.2
N$32
  Top 0.813: 13.01,8.73 13.05,8.69 X2.1
  Bottom 0.813: X2.3 11.78,3.69 13.01,4.92 13.01,8.41 13.29,8.69 | 13.29,8.69 13.33,8.73 | 13.29,8.69 X2.1 13.16,8.87 14.28,10 B1.AC1
N$33
  Top 0.406: C34.1 22.67,98.07 22.86,98.26 U$1.5
N$34
  Top 0.406: C31.1 35.37,86.64 U$1.11
N$35
  Top 0.406: C32.1 22.86,82.7 U$1.8
N$36
  Top 0.61: Q2.2 43.3,96.48
  Bottom 0.254: IC6.50 44.94,93.96 43.17,95.72 43.17,96.67
  Bottom 0.61: Q2.2 43.17,96.67 42.41,95.91 C18.1
N$37
  Bottom 0.254: Q2.1 48.25,96.67 48.76,97.18 IC6.51
  Bottom 0.61: Q2.1 47.94,96.67 47.17,95.91 C30.1
N$38  (via drill 0.5)
  Top 0.254: v57.14,93.81 57.14,86.19 57.78,85.56 LED2.C
  Bottom 0.254: IC6.61 57.39,95.65 57.14,95.4 v57.14,93.81
N$39  (via drill 0.5)
  Top 0.254: v58.1,94.77 60,92.86 60,89.69 60.11,89.79 LED3.C
  Bottom 0.254: IC6.62 58.04,94.82 v58.1,94.77
N$40
  Top 0.254: LED2.A R10.2
N$41
  Top 0.254: 65.4,90 LED3.A R9.2
N$42
  Bottom 0.254: R11.2 75.88,83.97 75.64,84.21 IC6.96
N$43
  Bottom 0.254: IC6.33 45.51,82.91 45.4,83.02
  Bottom 0.406: R12.2 42.75,81.96 43.81,83.02 45.4,83.02 C38.2
N$44  (via drill 0.5)
  Top 0.406: v33.02,80.48 35.24,80.48 35.55,80.16 LED4.A
  Bottom 0.406: Q3.C 31.11,82.07 32.7,80.48 v33.02,80.48
N$45
  Bottom 0.406: Q3.B 27.47,75.89 27.14,75.55 R13.1 27.14,73.01 R14.2
N$46  (via drill 0.5)
  Top 0.254: R17.2 v39.68,84.92
  Bottom 0.254: v39.68,84.92 43.81,84.92 44.39,85.51 IC6.37
N$47  (via drill 0.5)
  Top 0.254: R18.2 v40.95,85.88
  Bottom 0.254: v40.95,85.88 43.49,85.88 43.77,86.16 IC6.38
N$48  (via drill 0.5)
  Top 0.254: R19.2 v42.22,86.83
  Bottom 0.254: IC6.39 42.24,86.81 v42.22,86.83
N$49  (via drill 0.5)
  Top 0.254: R21.2 v43.49,87.78
  Bottom 0.254: IC6.40 43.82,87.46 v43.49,87.78
N$50  (via drill 0.5)
  Top 0.254: R22.2 44.76,88.1 44.13,88.73 v43.81,89.05
  Bottom 0.254: IC6.41 44.75,88.11 v43.81,89.05
N$51  (via drill 0.5)
  Top 0.254: R23.2 46.03,88.73 v44.76,90
  Bottom 0.254: IC6.42 46.01,88.76 v44.76,90
N$52  (via drill 0.5)
  Top 0.254: R24.2 47.3,89.05 46.35,90 v46.03,90
  Bottom 0.254: IC6.43 46.63,89.41 v46.03,90
P0.14  (via drill 0.5)
  Top 0.254: R1.2 56.19,60.16 v56.51,60.48 57.14,59.84 57.14,56.35 56.64,55.84 SJ2.2 54.29,55.72 56.83,55.72 57.14,55.4 57.14,39.52 57.78,38.89 v59.37,38.89 | SV1.44 86.04,32.22 81.91,32.22 78.73,29.05 68.26,29.05 67.94,28.73 66.35,28.73 61.27,33.81 v58.73,33.81
  Bottom 0.254: IC3.92 58.06,62.03 v56.51,60.48 | v58.73,33.81 59.37,34.44 v59.37,38.89
P0.21  (via drill 0.5)
  Top 0.254: v67.31,30.32 78.73,30.32 83.18,34.76 86.04,34.76 SV1.42
  Bottom 0.254: IC3.4 64.56,39.73 67.62,36.66 67.62,30.63 v67.31,30.32
P0.22  (via drill 0.5)
  Top 0.254: v66.04,30.32 66.99,29.36 67.62,29.36 67.94,29.68 78.73,29.68 82.55,33.49 SV1.43
  Bottom 0.254: IC3.5 64.06,39.59 66.67,36.98 66.67,30.95 v66.04,30.32
RD2  (via drill 0.5)
  Top 0.254: SV1.40 86.04,37.3 82.55,37.3 81.91,36.66 81.91,34.76 78.73,31.59 77.78,31.59 77.15,32.22 v65.72,32.22
  Bottom 0.254: IC3.6 63.56,39.45 66.04,36.98 66.04,32.54 v65.72,32.22
SCK1  (via drill 0.5)
  Top 0.254: v63.81,63.97 v66.99,63.97 | v72.39,68.41 72.39,67.78 76.51,63.65 v77.15,63.65 | v79.69,64.29 80.01,64.29 81.59,62.7 81.59,57.62 80.96,56.98 80.96,51.91 81.91,50.95 81.91,48.73 84.45,46.19 SV1.33
  Bottom 0.254: IC3.101 62.56,63.36 63.18,63.97 v63.81,63.97 | v66.99,63.97 70.16,63.97 70.8,64.6 70.8,66.83 v72.39,68.41 | v77.15,63.65 78.73,63.65 79.37,64.29 v79.69,64.29
SCL  (via drill 0.5)
  Top 0.254: v54.92,50.95 54.92,44.29 55.24,43.97 v55.24,39.2 | v55.56,36.66 56.19,36.03 60.95,36.03 62.54,34.44 76.83,34.44 77.78,33.49 78.73,33.49 80.01,34.76 80.01,40.48 80.64,41.11 SV1.37
  Bottom 0.254: IC3.50 47.28,49.39 47.62,49.05 48.57,49.05 50.48,50.95 v54.92,50.95 | v55.56,36.66 55.24,36.98 v55.24,39.2
SDA  (via drill 0.5)
  Top 0.254: v53.97,52.54 53.97,50.32 54.29,50 54.29,43.97 54.6,43.65 54.6,39.84 v53.97,39.2 | v54.29,36.66 54.29,36.35 55.24,35.4 60.95,35.4 62.54,33.81 76.83,33.81 77.78,32.86 78.73,32.86 80.64,34.76 80.64,38.89 81.59,39.84 86.04,39.84 SV1.38
  Bottom 0.254: IC3.58 47.2,53.39 47.62,53.81 52.7,53.81 v53.97,52.54 | v54.29,36.66 53.97,36.98 v53.97,39.2
SSEL1  (via drill 0.5)
  Top 0.254: v79.37,58.57 79.05,58.26 79.05,51.59 80.01,50.63 80.01,48.73 81.59,47.14 81.59,43.02 82.23,42.38 86.04,42.38 SV1.36
  Bottom 0.254: IC3.123 72.6,53.39 73.02,53.81 73.66,53.81 74.61,54.76 75.56,54.76 v79.37,58.57
TD2  (via drill 0.5)
  Top 0.254: v65.08,31.27 77.15,31.27 77.47,30.95 78.73,30.95 82.55,34.76 82.55,35.4 83.18,36.03 SV1.41
  Bottom 0.254: IC3.8 62.56,39.82 65.4,36.98 65.4,33.81 64.77,33.17 64.77,31.59 v65.08,31.27
V18  (via drill 0.5)
  Top 0.254: 46.98,41.43 v45.71,41.43 | v66.67,60.8 66.04,60.8 65.4,60.16 65.4,59.52 65.08,59.21 64.77,59.21 64.13,58.57 64.13,55.72 63.49,55.08 | 63.49,55.08 C26.1 | 63.49,55.08 63.81,55.08 v64.77,54.13 | v64.45,49.37 64.45,47.78 C24.1 65.4,47.78 66.04,47.14 66.04,44.92 v66.99,43.97 67.62,43.33 v76.2,43.33 | v50.48,46.83 50.48,43.33 49.84,42.7 48.25,42.7 46.98,41.43 | 46.98,41.43 C25.1
  Top 0.406: IC5.2 v35.24,8.41 33.65,8.41 32.7,9.36 32.7,11.27 31.43,12.54 31.43,14.12 C5.+
  Bottom 0.254: IC3.37 46.22,42.89 45.71,42.38 v45.71,41.43 | IC3.110 67.58,59.89 v66.67,60.8 | IC3.143 67.57,43.39 v66.99,43.97 | v64.77,54.13 64.77,49.68 v64.45,49.37 55.88,49.37 53.97,47.46 51.11,47.46 v50.48,46.83
  Bottom 0.406: R4.2 38.86,7.96 38.73,8.09 | 38.73,8.09 38.41,8.41 v35.24,8.41 | 38.73,8.09 40.95,8.09 41.59,7.46 41.59,5.87 43.17,4.28 59.05,4.28 76.2,21.11 v76.2,43.33 | C5.+ 31.43,14.12 31.3,14.25 C17.1
V33  (via drill 0.5, 0.6)
  Top 0.254: v42.54,26.19 42.44,26.09 42.44,25.02 | 49.52,50 49.21,50 | C9.1 62.54,59.52 63.49,59.52 v64.13,60.16 | C8.1 65.72,58.57 v66.99,58.57 | 48.57,54.13 C10.1 | v50.48,61.11 50.48,60.8 | v48.89,44.29 C11.1 | v51.75,42.38 C12.1 | v66.35,42.06 66.35,43.02 65.72,43.65 65.08,43.65 C14.1 | MMC1.4 17.51,66.14 v18.09,65.56 18.73,66.19 v22.54,66.19 | R1.1 54.6,58.57 v56.19,58.57 | IC2.29 68.33,21.82 65.93,19.42 IC2.23 65.93,8.83 66.04,8.73 C2.1 60.32,8.73 | 59.68,8.73 C1.1 | IC1.50 28.04,32.75 v28.25,32.54 | IC1.14 v35.24,26.82 36.51,26.82 36.84,26.49 IC1.16 | 60.33,10.64 IC2.16 | IC1.29 44.81,37.03 44.76,36.98 44.84,36.91 44.84,35.79 | 25.64,26.75 25.64,25.31 25.71,25.23 25.64,25.16 IC1.2 25.64,24.99 25.71,24.92 25.64,24.84 25.64,24.04 | 42.44,25.02 IC1.23 | 42.44,25.02 42.54,24.92 | 51.48,23.06 51.43,23.01 | 51.48,23.06 IC2.50 | 51.53,23.11 51.48,23.06 | 49.21,50 v47.94,50 | 49.21,50 49.21,51.91 v48.25,52.86 48.25,53.81 48.57,54.13 | 48.57,54.13 48.57,56.03 49.84,57.3 49.84,59.21 R20.1 | 49.52,50 C22.1 | v49.21,48.41 49.21,49.68 49.52,50 | v60,60.8 C23.1 v60,60.8 | v59.68,42.06 C13.1 v59.68,42.06
  Top 0.305: 42.44,26.09 43.17,26.82 50.16,26.82 51.53,25.45 51.53,23.11 | 25.64,26.75 25.71,26.82 25.71,27.78 28.04,30.1 28.04,32.86 v28.25,32.54 | IC2.50 51.53,22.28 v52.06,21.74 | IC2.2 49.13,11.19 49.21,11.27 49.21,10.31 48.57,9.68 v48.25,9.68 | v56.83,15.39 58.73,13.49 IC2.14 58.73,10.31 59.37,9.68 59.68,9.68 | 60.33,10.64 60.33,10.33 59.68,9.68 | 60.32,8.73 59.68,8.73 59.68,9.68 | IC2.29 68.33,23.72 69.21,24.6 77.78,24.6 79.05,25.87 SV1.49
  Top 0.406: v25.71,23.96 25.64,24.04 | IC4.2 25.08,16.98 25.71,17.62 | C4.+ 25.71,20.16 25.71,17.62 | 25.71,17.62 26.35,16.98 27.94,16.98 28.25,16.66 R5.2 | v44.76,35.71 44.84,35.79 | v66.04,54.13 R6.1 | 51.75,59.52 C21.1 51.75,59.21 R20.1 50.48,59.21 v50.48,61.11 | v93.66,61.43 93.66,27.78 v93.66,27.46
  Bottom 0.254: 42.54,33.81 44.45,35.71 v44.76,35.71 46.35,34.12 48.25,34.12 48.89,34.76 48.89,37.62 51.06,39.79 IC3.31 51.06,41.7 v51.75,42.38 51.75,43.33 | 42.54,33.81 v42.54,26.19 35.87,26.19 v35.24,26.82 | 42.54,33.81 42.54,31.59 | IC3.94 59.06,61.73 v60,60.8 60,59.84 | 50.56,61.2 IC3.77 | 50.56,61.2 v50.48,61.11 50.48,60.8 | 50.56,61.2 50.56,60.71 52.7,58.57 v56.19,58.57 56.83,58.57 57.78,59.52 59.68,59.52 60,59.84 | IC3.51 47.82,49.89 v47.94,50 | IC3.104 64.06,60.23 v64.13,60.16 64.13,59.84 | IC3.112 67.3,58.89 v66.99,58.57 66.35,58.57 | 64.13,59.84 64.13,59.52 65.08,58.57 66.35,58.57 | 60,59.84 60.32,59.52 63.81,59.52 64.13,59.84 | IC3.57 48.22,52.89 v48.25,52.86 | IC3.39 48.49,43.89 v48.89,44.29 | v48.89,44.29 50.79,44.29 51.75,43.33 | IC3.14 59.56,41.94 v59.68,42.06 59.68,43.33 | 51.75,43.33 52.7,44.29 58.73,44.29 59.68,43.33 | IC3.2 65.56,41.27 v66.35,42.06 66.35,43.33 65.4,44.29 60.64,44.29 59.68,43.33 | 66.36,55.39 IC3.119 | 66.36,55.39 66.04,55.72 66.04,58.26 66.35,58.57 | v18.09,65.56 18.09,37.94 18.73,37.3 18.73,29.68 20,28.41 20,25.87 20.32,25.55 21.59,25.55 | 66.36,55.39 66.34,55.39 66.04,55.08 v66.04,54.13 | 49.21,10.31 49.21,13.17 49.52,13.49 56.19,13.49 56.83,14.12 v56.83,15.39 | v48.89,44.29 48.89,48.09 v49.21,48.41 | 22.86,75.4 R13.2 | 22.86,75.4 22.54,75.72 22.54,79.84 23.17,80.48 24.76,80.48 25.39,81.11 25.39,82.38 26.03,83.02 27.3,83.02 Q3.E | v22.54,66.19 22.54,75.08 22.86,75.4 | D2.C 93.66,76.99 93.77,77.1 | D3.C 93.77,74.97 93.66,75.08 93.77,75.19
  Bottom 0.305: v28.25,32.54 31.43,29.36 33.33,29.36 35.24,27.46 v35.24,26.82 | v48.25,9.68 48.57,9.68 49.21,10.31 | v52.06,21.74 52.06,19.2 52.7,18.57 56.19,18.57 56.83,17.93 v56.83,15.39
  Bottom 0.406: C20.1 21.59,23.33 21.48,23.43 IC7.16 21.59,25.55 24.12,25.55 v25.71,23.96 25.65,23.9 C4.+ 25.71,20.16 25.53,19.97 C16.1 | SV1.49 SV1.50 92.7,25.87 93.66,26.82 v93.66,27.46 | 93.77,77.1 D1.C | 93.77,75.19 D2.C | D3.C 93.77,72.65 93.66,72.54 D4.C 93.77,70.52 93.98,70.32 D5.C 93.77,68.62 93.98,68.41 93.77,68.21 D6.C 93.77,66.3 93.66,66.19 93.77,66.08 D7.C 93.77,64.08 93.66,63.97 93.77,63.86 D8.C 93.77,61.54 v93.66,61.43
VCC  (via drill 0.5)
  Top 0.254: v66.35,81.11 v60.64,81.11 51.11,81.11 50.79,81.43 v50.79,82.7 50.79,89.05 51.43,89.69 | 51.43,89.69 50.79,90.32 v50.79,91.27 | 51.43,89.69 C35.1 | 71.88,85.75 72.07,85.56 R10.1 71.75,85.56 | R9.1 72.07,90 72.39,89.37
  Top 0.406: 71.88,85.75 R9.1 | 72.39,89.37 v74.93,89.37
  Top 0.61: 70.48,82.38 v68.89,82.38 | 70.48,82.38 71.75,83.65 71.75,85.56 | 70.48,82.38 70.8,82.07 79.69,82.07 80.32,82.7 80.32,83.65 80.96,84.29 SV1.3 | IC4.3 20.4,19.29 20,18.89 20,13.49 21.59,11.9 21.59,8.41 22.54,7.46 31.75,7.46 33.02,6.18 37.14,6.18 37.22,6.11 IC5.3 37.55,6.1 40.63,3.01 68.26,3.01 70.16,4.92 IC8.OUT | C37.+ 77.85,18.95 79.05,20.16 89.43,20.16 arc45 89.6,20.23 90.48,21.11 90.48,83.23 arc45 90.41,83.41 89.53,84.29 SV1.4
  Bottom 0.254: IC6.15 60.64,76.99 | IC6.17 59.34,76.99 59.99,76.99 | 59.99,76.99 IC6.16 | 60.64,76.99 59.99,76.99 | v60.64,81.11 60.64,76.99 | IC6.57 54.79,98.58 59.99,98.58 | 59.99,98.58 IC6.65 59.99,92.85 59.05,91.91 51.43,91.91 v50.79,91.27 50.06,92.01 IC6.47 | IC6.70 63.24,98.58 59.99,98.58 | 49.84,82.26 50.35,82.26 v50.79,82.7 | 66.5,81.11 66.5,81.89 66.99,82.38 v68.89,82.38 | IC6.89 74.27,88.76 v74.93,89.37 | C38.1 45.5,81.22 45.89,81.61 IC6.31 | C37.+ 77.85,17.36 77.78,17.3
  Bottom 0.406: IC6.6 66.5,81.11 v66.35,81.11 | IC6.32 49.84,82.26 49.84,81.61 IC6.31
  Bottom 0.61: C36.1 74.42,4.79 74.29,4.92 IC8.OUT 72.07,4.92 71.12,5.87 71.12,12.85 72.39,14.12 76.51,14.12 77.78,15.39 77.78,17.3 77.78,17.62
  Bottom 0.813: SV1.4 SV1.3
VIN
  Top 0.406: LED1.A 10.79,16.03 13.01,13.81 17.14,13.81 19.68,11.27 19.68,5.87 20.63,4.92 B1.+
  Bottom 0.406: 26.03,4.92 C15.1
  Bottom 0.61: C19.+ 30.16,4.92 33.65,1.42 79.05,1.42 80.64,3.01 80.64,8.41 79.05,10 IC8.IN
  Bottom 0.813: B1.+ 26.03,4.92 C19.+

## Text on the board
Bottom: C= Ulrich Radig 2005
